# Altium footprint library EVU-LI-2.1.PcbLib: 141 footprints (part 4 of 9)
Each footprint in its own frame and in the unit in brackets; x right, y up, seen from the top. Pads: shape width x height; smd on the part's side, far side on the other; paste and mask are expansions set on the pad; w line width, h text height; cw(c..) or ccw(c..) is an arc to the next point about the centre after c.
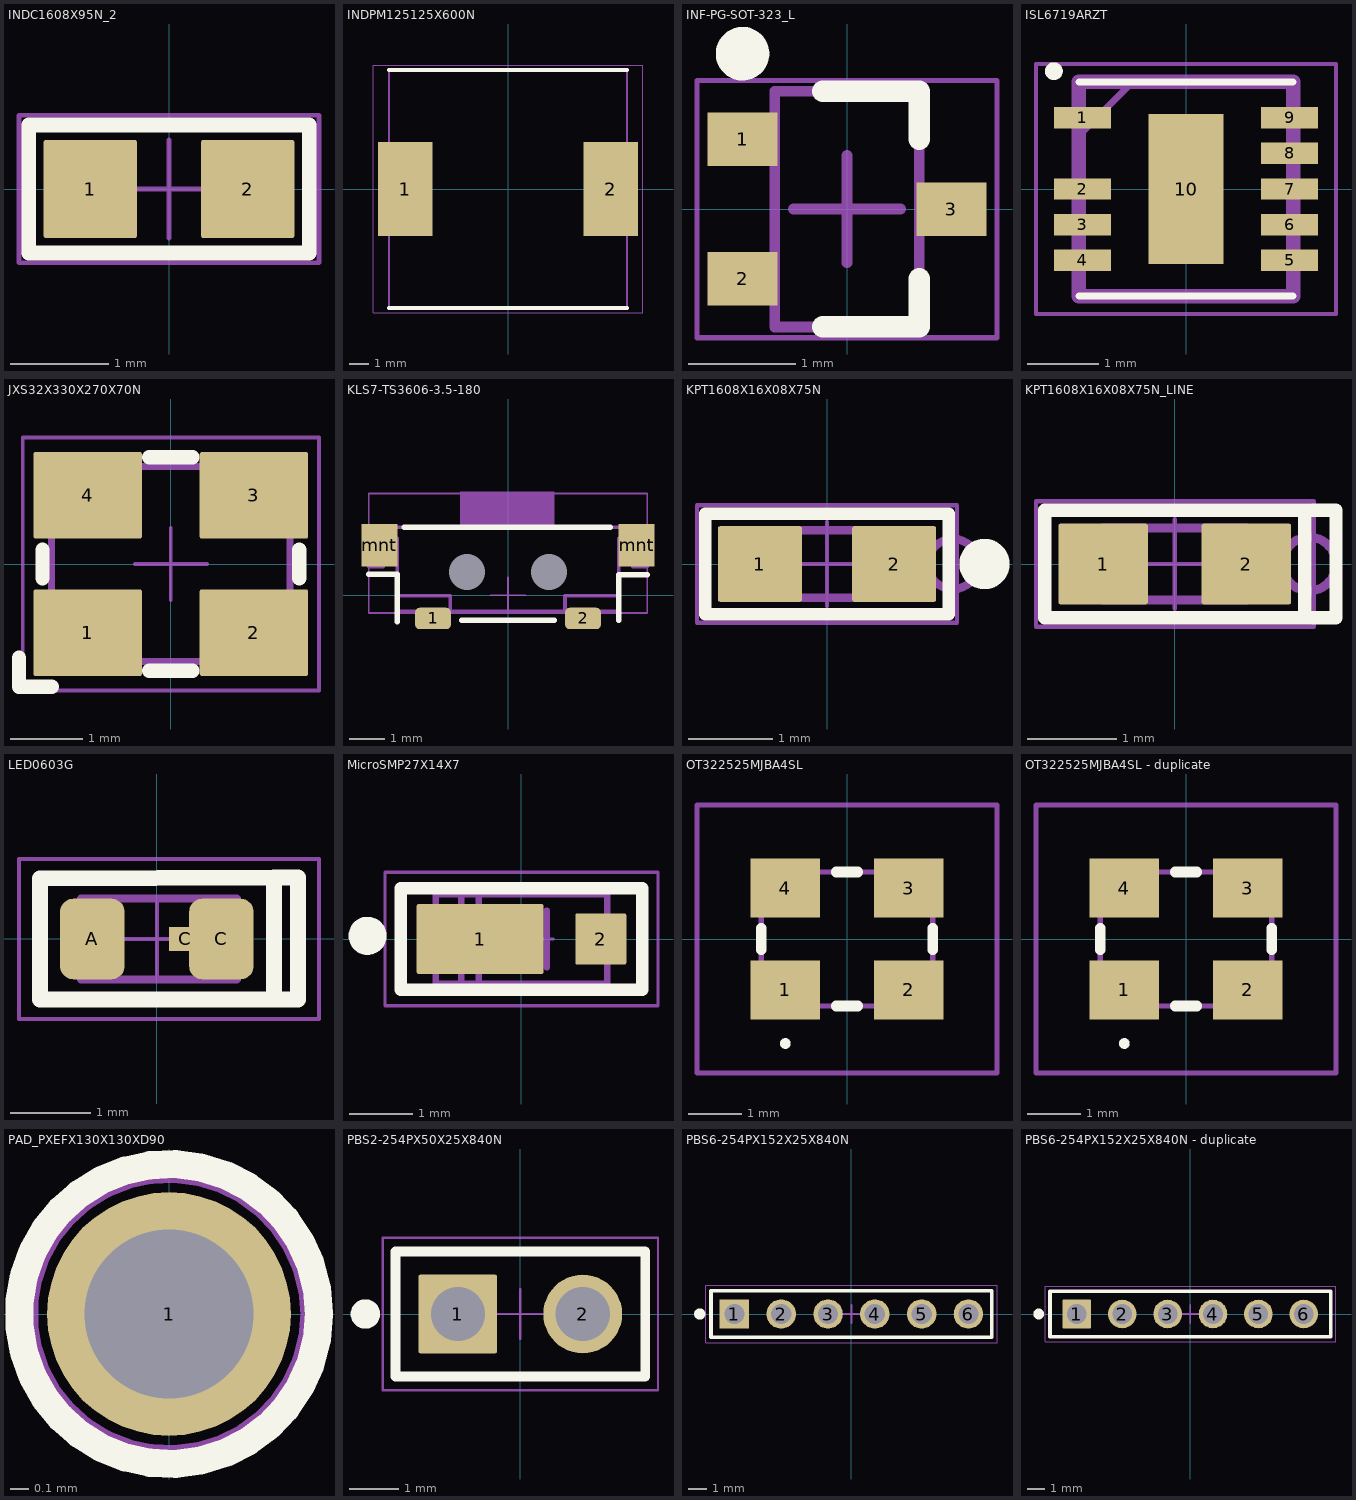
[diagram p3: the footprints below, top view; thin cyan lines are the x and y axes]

## INDC1608X95N_2 [mm]
pads (2):
  rrect5% 0.95x1 smd mask+0.07: 1(-0.8,0) 2(0.8,0)
Top Overlay:
  lines w0.15: -1.425,-0.65 -1.425,0.65 1.425,0.65 1.425,-0.65 -1.425,-0.65
Top Assembly:
  lines w0.1: -1.45,-0.65 -1.45,0.65 1.45,0.65 1.45,-0.65 -1.45,-0.65
Top Designator:
  text ".Designator" at -3.25,-0.3 h1.5
Top Courtyard:
  lines w0.05: -0.5,0 0.5,0 ; 0,-0.5 0,0.5 ; -1.525,-0.75 -1.525,0.75 1.525,0.75 1.525,-0.75 -1.525,-0.75
3D body "BLM18__TN1.STEP": height 0.65, standoff 0, extent -0.875,-0.475 0.875,0.475

## INDPM125125X600N [mm]
pads (2):
  rect 2.85x4.95 smd: 1(-5.4,0) 2(5.4,0)
Top Overlay:
  lines w0.2: -6.25,-6.25 6.25,-6.25 ; -6.25,6.25 6.25,6.25
Mechanical 13:
  lines w0.1: -6.25,-6.25 -6.25,6.25 6.25,6.25 6.25,-6.25 -6.25,-6.25
Top Courtyard:
  lines w0.05: -7.075,-6.5 -7.075,6.5 7.075,6.5 7.075,-6.5 -7.075,-6.5
3D body "DR125-220-R.stp": height 5.95, standoff 0, extent -6,-6 6,6

## INF-PG-SOT-323_L [mm] "SOT3, 3-Leads, Body 2x1.25mm, Pitch 0.65mm, IPC High Density"
height 1
pads (3):
  rect 0.65x0.5 smd: 1(-0.975,0.65) 2(-0.975,-0.65) 3(0.975,0)
Top Overlay:
  circle w0.25: c-0.975,1.45 r0.125
  lines w0.2: -0.225,-1.1 0.675,-1.1 0.675,-0.65 ; -0.225,1.1 0.675,1.1 0.675,0.65
Mechanical 13:
  lines w0.1: -0.675,-1.1 -0.675,1.1 0.675,1.1 0.675,-1.1 -0.675,-1.1
Top Courtyard:
  lines w0.05: -1.4,-1.2 -1.4,1.2 1.4,1.2 1.4,-1.2 -1.4,-1.2
  lines w0.1: -0.5,0 0.5,0 ; 0,-0.5 0,0.5
3D body: height 1, standoff 0.1, extent -0.675,-1.1 0.675,1.1

## ISL6719ARZT [mm]
pads (10):
  rect 0.8x0.3 smd: 1(-1.45,1) 2(-1.45,0) 3(-1.45,-0.5) 4(-1.45,-1) 5(1.45,-1) 6(1.45,-0.5) 7(1.45,0) 8(1.45,0.5) 9(1.45,1)
  rect 1.05x2.1 smd: 10(0,0)
Top Overlay:
  lines w0.1: -1.5,-1.5 1.5,-1.5 ; -1.5,1.5 1.5,1.5
  lines w0.125: -1.913,1.649 cw(c-1.85,1.649) -1.788,1.649 cw(c-1.85,1.649) -1.913,1.649
Mechanical 13:
  lines w0.1: -1.5,0.75 -0.75,1.5
  lines w0.2: -1.5,-1.5 1.5,-1.5 1.5,1.5 -1.5,1.5 -1.5,-1.5
Top Courtyard:
  lines w0.05: -2.1,-1.75 2.1,-1.75 2.1,1.75 -2.1,1.75 -2.1,-1.75

## JXS32X330X270X70N [mm]
pads (4):
  rrect5% 1.5x1.2 smd mask+0.07: 1(-1.15,-0.95) 2(1.15,-0.95) 3(1.15,0.95) 4(-1.15,0.95)
Top Overlay:
  lines w0.2: -2.1,-1.3 -2.1,-1.7 -1.65,-1.7 ; -1.775,-0.2 -1.775,0.2 ; -0.3,-1.475 0.3,-1.475 ; -0.3,1.475 0.3,1.475 ; 1.775,-0.2 1.775,0.2
Top Assembly:
  lines w0.1: -1.65,-1.35 -1.65,1.35 1.65,1.35 1.65,-1.35 -1.65,-1.35
Top Designator:
  text ".Designator" at -3.25,-0.3 h1.5
Mechanical 9:
  text ".MARK" at -1.65,-0.39 h1.2
Top Courtyard:
  lines w0.05: -0.5,0 0.5,0 ; 0,-0.5 0,0.5 ; -2.05,-1.75 -2.05,1.75 2.05,1.75 2.05,-1.75 -2.05,-1.75
3D body "JXS32.STEP": height 0.75, standoff 0, extent -1.65,-1.35 1.65,1.35
3D body: height 0.76, standoff 0.75, extent -1.422,-1.149 -0.725,-0.451

## KLS7-TS3606-3.5-180 [mm] "Tact Switch 3x6"
height 4.6
pads (6):
  rrect40% 1x0.6 smd: 1(-2.1,-0.65) 2(2.1,-0.65)
  round 0 hole 1: 10(-1.15,0.65) 10(1.15,0.65)
  rect 1x1.2 smd: mnt(-3.6,1.4) mnt(3.6,1.4)
Top Overlay:
  lines w0.15: -3.9,0.59 -3.1,0.59 -3.1,-0.74 ; -2.905,1.9 2.87,1.9 ; -1.3,-0.7 1.3,-0.7 ; 3.1,-0.7 3.1,0.57 3.9,0.57
Top Assembly:
  rectangle: -1.34,1.9 1.3,2.9
  region: -1.6,-0.45 -2.6,-0.45 -2.6,-0.8 -1.6,-0.8
  region: 2.595,-0.45 1.595,-0.45 1.595,-0.8 2.595,-0.8
  lines w0.1: -3.9,0.8 -3.5,0.8 -3.5,1.6 -3.1,1.6 -3.1,0.8 ; -3.9,0.834 -3.9,1.9 3.9,1.9 3.9,0.8 3.5,0.8 3.5,1.6 3.1,1.6 3.1,0.8 3.1,-0.45 -3.1,-0.45 -3.1,0.834 ; -3.1,-0.018 -1.622,-0.018 -1.622,-0.45 -1.6,-0.45 ; 1.595,-0.45 1.595,-0.018 3.1,-0.018
  text ".Designator" at -2.814,0.611 h1.5
Top Value:
  text ".Comment" at -1.6,-0.2 h1
Top Courtyard:
  lines w0.05: -0.5,0 0.5,0 ; 0,-0.5 0,0.5 ; -3.9,-0.5 3.9,-0.5 3.9,2.85 -3.9,2.85 -3.9,-0.5
3D body "IT-1188E.STEP": height 3.5, standoff -0.7, extent -3.9,-0.75 3.9,2.85

## KPT1608X16X08X75N [mm]
pads (2):
  rrect5% 1x0.9 smd mask+0.07: 1(-0.8,0) 2(0.8,0)
Top Overlay:
  circle w0.3: c1.875,0 r0.15
  lines w0.15: -1.45,-0.6 -1.45,0.6 1.45,0.6 1.45,-0.6 -1.45,-0.6
Top Assembly:
  circle w0.1: c1.5,0 r0.3
  lines w0.1: 0.55,-0.4 0.55,0.4 ; 0.65,-0.4 0.65,0.4 ; 0.75,-0.4 0.75,0.4 ; -0.8,-0.4 -0.8,0.4 0.8,0.4 0.8,-0.4 -0.8,-0.4
Top Designator:
  text ".Designator" at -3.275,-0.3 h1.5
Mechanical 9:
  text ".MARK" at -1.778,-0.354 h1.2
Top Courtyard:
  lines w0.05: -0.5,0 0.5,0 ; 0,-0.5 0,0.5 ; -1.55,-0.7 -1.55,0.7 1.55,0.7 1.55,-0.7 -1.55,-0.7
3D body: height 0.76, standoff 0.75, extent 0,-0.225 0.425,0.225
3D body "KPT-1608.STEP": height 0.75, standoff 0, extent -0.8,-0.4 0.8,0.4

## KPT1608X16X08X75N_LINE [mm]
pads (2):
  rrect5% 1x0.9 smd mask+0.07: 1(-0.8,0) 2(0.8,0)
Top Overlay:
  lines w0.15: 1.45,-0.6 1.8,-0.6 1.8,0.6 1.45,0.6 ; 1.45,-0.6 1.45,0.6 ; 1.45,-0.6 -1.45,-0.6 -1.45,0.6 1.45,0.6 ; 1.45,-0.6 1.45,0.6
Top Assembly:
  circle w0.1: c1.5,0 r0.3
  lines w0.1: 0.55,-0.4 0.55,0.4 ; 0.65,-0.4 0.65,0.4 ; 0.75,-0.4 0.75,0.4 ; -0.8,-0.4 -0.8,0.4 0.8,0.4 0.8,-0.4 -0.8,-0.4
Top Designator:
  text ".Designator" at -3.275,-0.3 h1.5
Mechanical 9:
  text ".MARK" at -1.778,-0.354 h1.2
Top Courtyard:
  lines w0.05: -0.5,0 0.5,0 ; 0,-0.5 0,0.5 ; -1.55,-0.7 -1.55,0.7 1.55,0.7 1.55,-0.7 -1.55,-0.7
3D body: height 0.76, standoff 0.75, extent 0,-0.225 0.425,0.225
3D body "KPT-1608.STEP": height 0.75, standoff 0, extent -0.8,-0.4 0.8,0.4

## LED0603G [mm] "SMD LED Green,  metric 1608"
height 0.85
pads (3):
  rrect40% 0.8x1 smd: A(-0.8,0) C(0.8,0)
  rect 0.4x0.3 smd: C(0.35,0)
Top Overlay:
  lines w0.2: 1.45,-0.75 1.75,-0.75 1.75,0.76 1.45,0.76 ; 1.45,-0.75 1.45,0.76 ; 1.45,-0.75 -1.45,-0.75 -1.45,0.749 1.45,0.76
Top Assembly:
  rectangle: 0.57,-0.5 0.96,0.5
  lines w0.1: -0.94,-0.5 0.99,-0.5 0.99,0.5 -0.94,0.5 -0.94,-0.5
  text ".Designator" at -1.511,-0.135 h0.7
Top Value:
  text ".Comment" at -0.997,-0.495 h0.4
Top Courtyard:
  lines w0.05: -0.5,0 0.5,0 ; 0,-0.5 0,0.5 ; -1.71,-0.99 2.01,-0.99 2.01,0.989 -1.71,0.989 -1.71,-0.99
3D body "User Library-LTST-C190GKT.STEP": height 0.9, standoff 0, extent -0.85,-0.45 0.85,0.45

## MicroSMP27X14X7 [mm]
pads (2):
  rrect5% 2x1.1 smd mask+0.07: 1(-0.65,0)
  rrect5% 0.8x0.8 smd mask+0.07: 2(1.25,0)
Top Overlay:
  circle w0.3: c-2.425,0.05 r0.15
  lines w0.2: -1.9,-0.8 1.9,-0.8 1.9,0.8 -1.9,0.8 -1.9,-0.8
Top Assembly:
  circle w0.1: c1.225,0 r0.3
  lines w0.1: -0.95,-0.7 -0.95,0.7 ; -0.675,-0.7 -0.675,0.7 ; 0.4,-0.45 0.4,0.45 ; -1.35,-0.7 -1.35,0.7 1.35,0.7 1.35,-0.7 -1.35,-0.7
Top Designator:
  text ".Designator" at -3.275,-0.3 h1.5
Mechanical 9:
  text ".MARK" at -1.778,-0.354 h1.2
Top Courtyard:
  lines w0.05: -0.5,0 0.5,0 ; 0,-0.5 0,0.5 ; -2.15,-1.05 2.15,-1.05 2.15,1.05 -2.15,1.05 -2.15,-1.05
3D body "MicroSMP.STEP": height 0.7, standoff 0, extent -1.35,-0.7 1.35,0.7
3D body: height 0.74, standoff 0.73, extent -1.013,-0.625 -0.825,0.625

## OT322525MJBA4SL [mm]
pads (4):
  rect 1.3x1.1 smd: 1(-1.15,-0.95) 2(1.15,-0.95) 3(1.15,0.95) 4(-1.15,0.95)
Top Overlay:
  lines w0.1: -1.15,-2 cw(c-1.15,-1.95) -1.15,-1.9 cw(c-1.15,-1.95) -1.15,-2
  lines w0.2: -1.6,-0.2 -1.6,0.2 ; -0.2,-1.25 0.2,-1.25 ; -0.2,1.25 0.2,1.25 ; 1.6,-0.2 1.6,0.2
Mechanical 13:
  lines w0.1: -1.6,-1.25 1.6,-1.25 1.6,1.25 -1.6,1.25 -1.6,-1.25
Top Courtyard:
  lines w0.1: -2.8,-2.5 2.8,-2.5 2.8,2.5 -2.8,2.5 -2.8,-2.5
3D body "OT322525MJBA4SL.stp": height 1.1, standoff 0, extent -1.69,-1.39 1.69,1.39

## OT322525MJBA4SL - duplicate [mm]
pads (4):
  rect 1.3x1.1 smd: 1(-1.15,-0.95) 2(1.15,-0.95) 3(1.15,0.95) 4(-1.15,0.95)
Top Overlay:
  lines w0.1: -1.15,-2 ccw(c-1.15,-1.95) -1.15,-1.9 ccw(c-1.15,-1.95) -1.15,-2
  lines w0.2: -1.6,-0.2 -1.6,0.2 ; -0.2,-1.25 0.2,-1.25 ; -0.2,1.25 0.2,1.25 ; 1.6,-0.2 1.6,0.2
Mechanical 13:
  lines w0.1: -1.6,-1.25 -1.6,1.25 1.6,1.25 1.6,-1.25 -1.6,-1.25
Top Courtyard:
  lines w0.1: -2.8,-2.5 -2.8,2.5 2.8,2.5 2.8,-2.5 -2.8,-2.5
3D body "OT322525MJBA4SL.stp": height 1.1, standoff 0, extent -1.69,-1.39 1.69,1.39

## PAD_PXEFX130X130XD90 [mm]
pads (1):
  round 1.3 hole 0.9 mask+0.07: 1(0,0)
Top Overlay:
  circle w0.15: c0,0 r0.8
Bottom Overlay:
  circle w0.15: c0,0 r0.8
  text ".Designator" at 3.275,-0.3 h1.5
Top Assembly:
  circle w0.1: c0,0 r0.75
Bottom Assembly:
  circle w0.1: c0,0 r0.75
Top Designator:
  text ".Designator" at -3.275,-0.3 h1.5
  text ".Designator" at 3.375,-0.325 h1.5

## PBS2-254PX50X25X840N [mil]
height 330.71
pads (2):
  rrect5% 63x63 hole 43.31 mask+2.76: 1(-50,0)
  round 63 hole 43.31 mask+2.76: 2(50,0)
Top Overlay:
  circle w11.81: c-124.02,0 r5.91
  lines w7.87: -100,-50 -100,50 100,50 100,-50 -100,-50
Top Assembly:
  lines w3.94: -100,-50 -100,50 100,50 100,-50 -100,-50
  text "1" at -126.57,-15.55 h59.06
Top Designator:
  text ".Designator" at -127.95,-11.81 h59.06
Top Courtyard:
  lines w1.97: -19.68,0 19.68,0 ; 0,-19.68 0,19.68 ; -110.24,-61.02 -110.24,61.02 110.24,61.02 110.24,-61.02 -110.24,-61.02
3D body "PBS-2.STEP": height 330.71, standoff -125.98, extent -100,-50 100,50

## PBS6-254PX152X25X840N [mil]
height 330.71
pads (6):
  rrect5% 63x63 hole 43.31 mask+2.76: 1(-250,0)
  round 63 hole 43.31 mask+2.76: 2(-150,0) 3(-50,0) 4(50,0) 5(150,0) 6(250,0)
Top Overlay:
  circle w11.81: c-324.02,0 r5.91
  lines w7.87: -300,-50 -300,50 300,50 300,-50 -300,-50
Bottom Overlay:
  circle w11.81: c-300,50 r5.91
Top Assembly:
  lines w3.94: -300,-50 -300,50 300,50 300,-50 -300,-50
  text "1" at -326.57,-15.55 h59.06
Top Designator:
  text ".Designator" at 127.95,11.81 h59.06
Top Courtyard:
  lines w1.97: -311.02,-61.02 -311.02,61.02 311.02,61.02 311.02,-61.02 -311.02,-61.02
  lines w3.94: -19.68,0 19.68,0 ; 0,-19.68 0,19.68
3D body "PBS-6.STEP": height 330.71, standoff -125.98, extent -300,-50 300,50

## PBS6-254PX152X25X840N - duplicate [mil]
height 330.71
pads (6):
  rrect5% 63x63 hole 43.31 mask+2.76: 1(-250,0)
  round 63 hole 43.31 mask+2.76: 2(-150,0) 3(-50,0) 4(50,0) 5(150,0) 6(250,0)
Top Overlay:
  circle w11.81: c-334,0 r5.91
  lines w7.87: -309,-50 309,-50 309,50 -309,50 -309,-50
Bottom Overlay:
  circle w11.81: c-311,50 r5.91
Top Assembly:
  lines w3.94: -311,-50 310,-50 310,50 -311,50 -311,-50
  text "1" at -326.57,-15.55 h59.06
Top Designator:
  text ".Designator" at 127.95,11.81 h59.06
Top Courtyard:
  lines w1.97: -319,-61.02 321,-61.02 321,61.02 -319,61.02 -319,-61.02
  lines w3.94: -19.68,0 19.68,0 ; 0,-19.68 0,19.68
3D body "PBS-6.step": height 334.65, standoff -118.11, extent -309.84,-50 309.84,48.43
